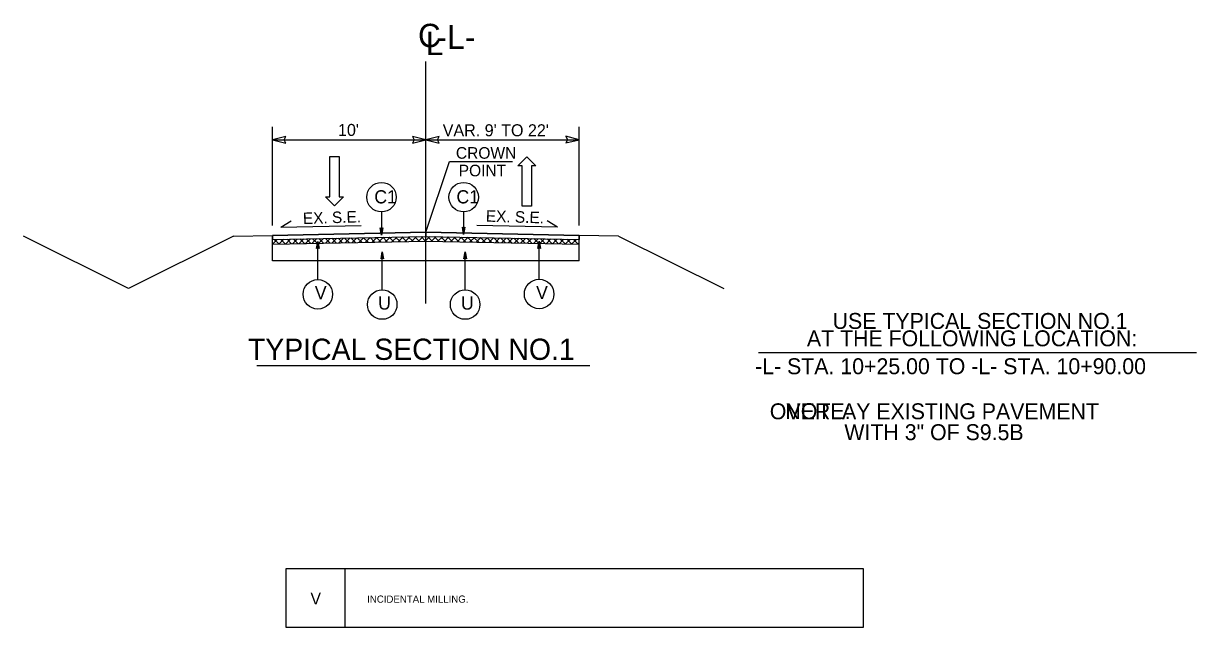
# Model space of a CAD drawing. Extents: x 573786 to 574032, y -53324 to -53148.
# Drawn here: x 573786.4 to 573862.9, y -53187.4 to -53148.1 of the extents above; entities that cross this region are included whole.
import ezdxf

# ---------------------------------------------------------------- set-up
doc = ezdxf.new("R2010")
doc.units = 0
for name, color, linetype in [('Prop Dimension', 7, 'Continuous'), ('Prop Dimension Text', 7, 'Continuous'), ('Prop Horizontal Alignment Curve and Spiral Data', 7, 'Continuous'), ('Prop Lane Arrow CELL', 7, 'Continuous'), ('Prop Pavement Schedule Description CELL', 7, 'Continuous'), ('Prop Shade Medium', 7, 'Continuous'), ('Typical Berm Information CELL', 7, 'Continuous'), ('Typical Grade Point Symbol CELL', 7, 'Continuous'), ('Typical ID Circle CELL', 7, 'Continuous'), ('Typical Pavement Slope CELL', 7, 'Continuous'), ('Typical Pavement Slope Information CELL', 7, 'Continuous'), ('Typical Slope Point Local CELL', 7, 'Continuous'), ('Typical Terminator CELL', 7, 'Continuous'), ('Typical Text Centerline CELL', 7, 'Continuous'), ('Typical Text Grade Point CELL', 7, 'Continuous'), ('Typical Text ID Circle CELL', 7, 'Continuous'), ('Typical Text Label CELL', 7, 'Continuous')]:
    doc.layers.add(name, color=color, linetype=linetype)

# ---------------------------------------------------------------- blocks, each defined once
blk = doc.blocks.new('TERMINATOR')
at = {"layer": 'Typical Terminator CELL'}
blk.add_lwpolyline([(-0.469, 0.081), (0, 0), (-0.471, -0.083), (-0.411, 0)], close=True, dxfattribs=at)

msp = doc.modelspace()

# ---------------------------------------------------------------- linework, layer by layer
at = {"layer": 'Prop Dimension'}
for p, q in [((573802.668, -53162.449), (573802.974, -53162.142)), ((573802.79, -53162.146), (573803.084, -53162.44)), ((573803.101, -53162.44), (573803.407, -53162.134)), ((573803.206, -53162.138), (573803.5, -53162.432)), ((573803.534, -53162.431), (573803.84, -53162.125)), ((573803.622, -53162.129), (573803.916, -53162.424)), ((573803.967, -53162.423), (573804.273, -53162.116)), ((573804.038, -53162.121), (573804.332, -53162.415)), ((573804.4, -53162.414), (573804.706, -53162.108)), ((573804.454, -53162.113), (573804.748, -53162.407)), ((573804.833, -53162.405), (573805.139, -53162.099)), ((573804.87, -53162.104), (573805.164, -53162.399)), ((573805.266, -53162.397), (573805.572, -53162.09)), ((573805.286, -53162.096), (573805.58, -53162.39)), ((573805.699, -53162.388), (573806.005, -53162.082)), ((573805.702, -53162.088), (573805.996, -53162.382)), ((573806.117, -53162.079), (573806.412, -53162.374)), ((573806.132, -53162.379), (573806.438, -53162.073)), ((573806.533, -53162.071), (573806.828, -53162.365)), ((573806.565, -53162.37), (573806.871, -53162.064)), ((573806.949, -53162.063), (573807.243, -53162.357)), ((573806.998, -53162.362), (573807.304, -53162.056)), ((573807.365, -53162.054), (573807.659, -53162.349)), ((573807.431, -53162.353), (573807.737, -53162.047)), ((573807.781, -53162.046), (573808.075, -53162.34)), ((573807.864, -53162.344), (573808.17, -53162.038)), ((573808.197, -53162.038), (573808.491, -53162.332)), ((573808.297, -53162.336), (573808.603, -53162.03)), ((573808.613, -53162.029), (573808.907, -53162.324)), ((573808.73, -53162.327), (573809.036, -53162.021)), ((573809.029, -53162.021), (573809.323, -53162.315)), ((573809.163, -53162.318), (573809.469, -53162.012)), ((573809.445, -53162.013), (573809.739, -53162.307)), ((573809.595, -53162.31), (573809.902, -53162.004)), ((573809.861, -53162.004), (573810.155, -53162.298)), ((573810.028, -53162.301), (573810.335, -53161.995)), ((573810.277, -53161.996), (573810.571, -53162.29)), ((573810.461, -53162.292), (573810.767, -53161.986)), ((573810.693, -53161.988), (573810.987, -53162.282)), ((573810.894, -53162.284), (573811.2, -53161.978)), ((573811.109, -53161.979), (573811.403, -53162.273)), ((573811.327, -53162.275), (573811.633, -53161.969)), ((573811.525, -53161.971), (573811.819, -53162.265)), ((573811.76, -53162.266), (573812.066, -53161.96)), ((573811.94, -53161.963), (573812.234, -53162.257)), ((573812.193, -53162.258), (573812.499, -53161.952)), ((573812.356, -53161.954), (573812.65, -53162.248)), ((573812.626, -53162.249), (573812.922, -53161.953)), ((573812.777, -53161.95), (573813.083, -53162.257)), ((573813.044, -53162.256), (573813.338, -53161.962)), ((573813.21, -53161.959), (573813.516, -53162.265)), ((573813.459, -53162.264), (573813.754, -53161.97)), ((573813.642, -53161.968), (573813.949, -53162.274)), ((573813.875, -53162.272), (573814.17, -53161.978)), ((573814.075, -53161.976), (573814.382, -53162.283)), ((573814.291, -53162.281), (573814.586, -53161.987)), ((573814.508, -53161.985), (573814.815, -53162.291)), ((573814.707, -53162.289), (573815.001, -53161.995)), ((573814.941, -53161.994), (573815.248, -53162.3)), ((573815.123, -53162.297), (573815.417, -53162.003)), ((573815.374, -53162.002), (573815.68, -53162.309)), ((573815.539, -53162.306), (573815.833, -53162.012)), ((573815.807, -53162.011), (573816.113, -53162.317)), ((573815.955, -53162.314), (573816.249, -53162.02)), ((573816.24, -53162.02), (573816.546, -53162.326)), ((573816.371, -53162.322), (573816.665, -53162.028)), ((573816.673, -53162.028), (573816.979, -53162.335)), ((573816.787, -53162.331), (573817.081, -53162.037)), ((573817.106, -53162.037), (573817.412, -53162.343)), ((573817.203, -53162.339), (573817.497, -53162.045)), ((573817.539, -53162.046), (573817.845, -53162.352)), ((573817.619, -53162.347), (573817.913, -53162.053)), ((573817.972, -53162.054), (573818.278, -53162.361)), ((573818.035, -53162.356), (573818.329, -53162.062)), ((573818.405, -53162.063), (573818.711, -53162.369)), ((573818.451, -53162.364), (573818.745, -53162.07)), ((573818.838, -53162.072), (573819.144, -53162.378)), ((573818.867, -53162.372), (573819.161, -53162.078)), ((573819.271, -53162.08), (573819.577, -53162.387)), ((573819.282, -53162.381), (573819.577, -53162.087)), ((573819.698, -53162.389), (573819.993, -53162.095)), ((573819.704, -53162.089), (573820.01, -53162.395)), ((573820.114, -53162.397), (573820.408, -53162.103)), ((573820.137, -53162.098), (573820.443, -53162.404)), ((573820.53, -53162.406), (573820.824, -53162.112)), ((573820.57, -53162.107), (573820.876, -53162.413)), ((573820.946, -53162.414), (573821.24, -53162.12)), ((573821.002, -53162.115), (573821.309, -53162.421)), ((573821.362, -53162.422), (573821.656, -53162.128)), ((573821.435, -53162.124), (573821.742, -53162.43)), ((573821.778, -53162.431), (573822.072, -53162.137)), ((573821.868, -53162.133), (573822.175, -53162.439)), ((573822.194, -53162.439), (573822.488, -53162.145)), ((573822.301, -53162.141), (573822.607, -53162.447)), ((573822.61, -53162.447), (573822.668, -53162.389))]:
    msp.add_line(p, q, dxfattribs=at)
at = {"layer": 'Prop Dimension Text'}
for p, q in [((573802.668, -53155.641), (573812.668, -53155.641)), ((573812.668, -53155.641), (573822.668, -53155.64)), ((573802.668, -53163.548), (573802.668, -53162.099)), ((573802.668, -53162.449), (573812.664, -53162.248)), ((573812.664, -53162.248), (573822.668, -53162.449)), ((573822.668, -53163.547), (573822.668, -53162.099)), ((573822.668, -53163.547), (573802.668, -53163.548))]:
    msp.add_line(p, q, dxfattribs=at)
at = {"layer": 'Prop Lane Arrow CELL'}
for p, q in [((573806.404, -53159.37), (573806.404, -53156.745)), ((573806.404, -53156.745), (573807.023, -53156.745)), ((573807.023, -53156.745), (573807.023, -53159.37)), ((573818.662, -53157.341), (573819.243, -53156.75)), ((573819.243, -53156.75), (573819.843, -53157.341)), ((573818.943, -53157.341), (573818.662, -53157.341)), ((573818.943, -53159.966), (573818.943, -53157.341)), ((573819.843, -53157.341), (573819.562, -53157.341)), ((573819.562, -53157.341), (573819.562, -53159.966)), ((573806.723, -53159.961), (573806.123, -53159.37)), ((573806.123, -53159.37), (573806.404, -53159.37)), ((573807.304, -53159.37), (573806.723, -53159.961)), ((573807.023, -53159.37), (573807.304, -53159.37)), ((573819.562, -53159.966), (573818.943, -53159.966))]:
    msp.add_line(p, q, dxfattribs=at)
at = {"layer": 'Prop Pavement Schedule Description CELL'}
msp.add_lwpolyline([(573807.41, -53187.448), (573803.563, -53187.448), (573803.563, -53183.6), (573841.183, -53183.6), (573841.183, -53187.448), (573807.41, -53187.448), (573807.41, -53183.6)], dxfattribs=at)
at = {"layer": 'Prop Shade Medium'}
for p, q in [((573802.668, -53161.876), (573812.668, -53161.676)), ((573812.668, -53161.676), (573802.668, -53161.876)), ((573802.673, -53162.098), (573802.668, -53161.876)), ((573802.668, -53162.149), (573812.665, -53161.948)), ((573812.665, -53161.948), (573812.668, -53161.948)), ((573812.668, -53161.676), (573822.668, -53161.876)), ((573812.668, -53161.948), (573812.668, -53161.676)), ((573822.668, -53161.876), (573812.668, -53161.676)), ((573812.668, -53161.676), (573812.668, -53161.948)), ((573812.668, -53161.948), (573822.668, -53162.149)), ((573822.668, -53162.099), (573822.668, -53161.876)), ((573822.668, -53162.149), (573822.668, -53162.099))]:
    msp.add_line(p, q, dxfattribs=at)
msp.add_lwpolyline([(573802.668, -53161.876), (573802.668, -53162.099), (573802.668, -53162.149)], dxfattribs=at)
at = {"layer": 'Typical Grade Point Symbol CELL'}
msp.add_line((573812.668, -53161.676), (573814.206, -53157.063), dxfattribs=at)
at = {"layer": 'Typical ID Circle CELL'}
for p, q in [((573809.779, -53160.35), (573809.779, -53161.854)), ((573815.133, -53160.35), (573815.133, -53161.818)), ((573805.629, -53164.757), (573805.629, -53162.272)), ((573820.053, -53164.741), (573820.053, -53162.256)), ((573809.826, -53165.429), (573809.826, -53162.943)), ((573815.229, -53165.429), (573815.229, -53162.943))]:
    msp.add_line(p, q, dxfattribs=at)
for centre in [(573809.779, -53159.389), (573815.133, -53159.389), (573805.629, -53165.719), (573820.053, -53165.703), (573809.826, -53166.39), (573815.229, -53166.39)]:
    msp.add_circle(centre, 0.962, dxfattribs=at)
at = {"layer": 'Typical Pavement Slope CELL'}
for p, q in [((573812.668, -53161.676), (573802.668, -53161.876)), ((573802.668, -53161.876), (573802.668, -53162.149)), ((573802.668, -53162.149), (573812.665, -53161.948)), ((573812.663, -53161.948), (573822.668, -53162.149)), ((573822.668, -53161.876), (573812.668, -53161.676)), ((573822.668, -53161.876), (573822.668, -53162.149))]:
    msp.add_line(p, q, dxfattribs=at)
at = {"layer": 'Typical Pavement Slope Information CELL'}
for p, q in [((573803.209, -53161.336), (573803.882, -53160.929)), ((573803.209, -53161.336), (573808.46, -53161.231)), ((573821.253, -53161.336), (573816.001, -53161.231)), ((573821.253, -53161.336), (573820.58, -53160.929))]:
    msp.add_line(p, q, dxfattribs=at)
at = {"layer": 'Typical Slope Point Local CELL'}
for p, q in [((573793.283, -53165.351), (573786.436, -53161.927)), ((573800.13, -53161.927), (573793.283, -53165.351)), ((573800.13, -53161.927), (573802.668, -53161.876)), ((573825.238, -53161.928), (573822.668, -53161.876)), ((573825.238, -53161.928), (573832.085, -53165.351))]:
    msp.add_line(p, q, dxfattribs=at)
at = {"layer": 'Typical Terminator CELL'}
for points in [[(573809.86, -53161.385), (573809.779, -53161.854), (573809.696, -53161.382), (573809.779, -53161.442)], [(573815.214, -53161.349), (573815.133, -53161.818), (573815.05, -53161.347), (573815.133, -53161.407)], [(573805.549, -53162.741), (573805.629, -53162.272), (573805.713, -53162.743), (573805.629, -53162.683)], [(573819.972, -53162.725), (573820.053, -53162.256), (573820.136, -53162.727), (573820.053, -53162.667)], [(573809.745, -53163.412), (573809.826, -53162.943), (573809.909, -53163.414), (573809.826, -53163.355)], [(573815.148, -53163.412), (573815.229, -53162.943), (573815.312, -53163.414), (573815.229, -53163.355)]]:
    msp.add_lwpolyline(points, close=True, dxfattribs=at)
at = {"layer": 'Typical Text Centerline CELL'}
for p, q in [((573812.668, -53152.444), (573812.668, -53150.546)), ((573812.668, -53153.838), (573812.668, -53152.444)), ((573812.668, -53166.318), (573812.668, -53153.838)), ((573802.668, -53161.228), (573802.668, -53154.796)), ((573822.668, -53161.227), (573822.668, -53154.796))]:
    msp.add_line(p, q, dxfattribs=at)
at = {"layer": 'Typical Text Grade Point CELL'}
msp.add_line((573814.206, -53157.063), (573818.312, -53157.063), dxfattribs=at)
at = {"layer": 'Typical Text Label CELL'}
for p, q in [((573834.353, -53169.52), (573862.913, -53169.518)), ((573801.643, -53170.373), (573823.368, -53170.372))]:
    msp.add_line(p, q, dxfattribs=at)

# ---------------------------------------------------------------- block references
at = {"layer": 'Prop Dimension Text'}
for p, xscale, yscale, rotation in [((573802.668, -53155.641), 1.8461659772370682, -2.6498242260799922, -179.9976856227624), ((573812.668, -53155.641), 1.8461659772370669, -2.649824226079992, 0.002314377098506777), ((573812.668, -53155.641), 1.8461659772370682, -2.6498242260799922, -179.9976856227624), ((573822.668, -53155.64), 1.8461659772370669, -2.649824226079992, 0.002314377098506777)]:
    msp.add_blockref('TERMINATOR', p, dxfattribs=dict(at, xscale=xscale, yscale=yscale, rotation=rotation))

# ---------------------------------------------------------------- texts
for s, height, p in [("10'", 0.7834, (573806.942, -53155.396)), ("VAR. 9' TO 22'", 0.78342, (573813.769, -53155.418))]:
    msp.add_text(s, height=height, rotation=0.00231, dxfattribs=at).set_placement(p)
at = {"layer": 'Prop Horizontal Alignment Curve and Spiral Data'}
msp.add_text('-L-', height=1.5672, rotation=0.00231, dxfattribs=at).set_placement((573813.342, -53149.726))
at = {"layer": 'Prop Pavement Schedule Description CELL'}
for s, height, p in [('V', 0.768, (573805.147, -53185.944)), ('INCIDENTAL MILLING.', 0.47025, (573808.843, -53185.829))]:
    msp.add_text(s, height=height, dxfattribs=at).set_placement(p)
at = {"layer": 'Typical Berm Information CELL'}
for rotation, p in [(1.81073, (573804.665, -53161.145)), (358.18927, (573816.571, -53160.981))]:
    msp.add_text('EX. S.E.', height=0.75, rotation=rotation, dxfattribs=at).set_placement(p)
at = {"layer": 'Typical Text Centerline CELL'}
for s, height, rotation, p in [('C', 1.523, 0.00231, (573812.161, -53149.607)), ('L', 1.524, 359.94921, (573812.667, -53150.127))]:
    msp.add_text(s, height=height, rotation=rotation, dxfattribs=at).set_placement(p)
at = {"layer": 'Typical Text Grade Point CELL'}
for s, p in [('CROWN', (573814.628, -53156.882)), ('POINT', (573814.811, -53158.029))]:
    msp.add_text(s, height=0.7573, rotation=0.00231, dxfattribs=at).set_placement(p)
at = {"layer": 'Typical Text ID Circle CELL'}
for s, height, p in [('C1', 0.8608, (573809.31, -53159.795)), ('C1', 0.8608, (573814.664, -53159.795)), ('V', 0.861, (573805.431, -53166.049)), ('V', 0.861, (573819.855, -53166.033)), ('U', 0.861, (573809.557, -53166.72)), ('U', 0.861, (573814.959, -53166.72))]:
    msp.add_text(s, height=height, rotation=360, dxfattribs=at).set_placement(p)
at = {"layer": 'Typical Text Label CELL'}
for s, height, p in [('USE TYPICAL SECTION NO.1', 1.03895, (573839.188, -53167.978)), ('AT THE FOLLOWING LOCATION:', 1.03895, (573837.512, -53169.11)), (' TYPICAL SECTION NO.1 ', 1.38527, (573800.554, -53169.997)), ('-L- STA. 10+25.00 TO -L- STA. 10+90.00', 1.03895, (573834.134, -53170.93)), ('         OVERLAY EXISTING PAVEMENT', 1.03895, (573831.617, -53173.869)), ('NOTE: ', 1.039, (573836.108, -53173.859)), ('  WITH 3" OF S9.5B', 1.03895, (573839.181, -53175.23))]:
    msp.add_text(s, height=height, rotation=0.00231, dxfattribs=at).set_placement(p)

doc.saveas('drawing.dxf')
